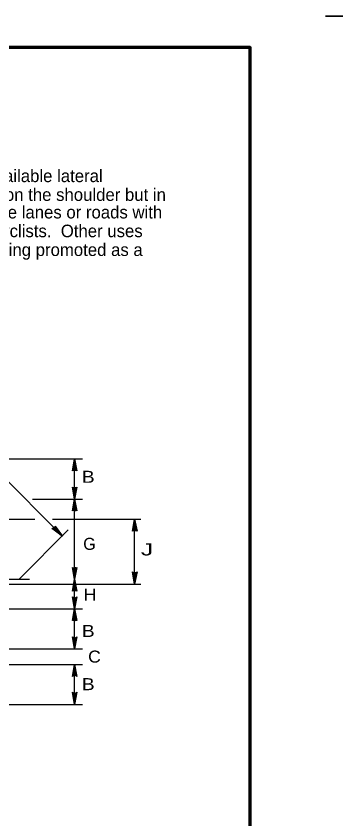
# Model space of a CAD drawing. Extents: x -0.018 to 0.195, y -0.006 to 0.263.
# Drawn here: x 0.1297 to 0.195, y 0.1026 to 0.2627 of the extents above; entities that cross this region are included whole.
import ezdxf
from ezdxf.enums import TextEntityAlignment as Align

# ---------------------------------------------------------------- set-up
doc = ezdxf.new("R2010")
doc.units = 0
doc.header["$LTSCALE"] = 0.00096
doc.linetypes.add('DOT_DASHED', pattern=[7.7, 5, -1.2, 0.3, -1.2])
doc.layers.add('1', color=7, linetype='Continuous', lineweight=25)
doc.layers.add('3', color=7, linetype='Continuous', lineweight=35)

msp = doc.modelspace()

# ---------------------------------------------------------------- linework, layer by layer
at = {"layer": '1', "lineweight": 35}
msp.add_line((0.195, 0.26275), (0.1915, 0.26275), dxfattribs=at)
at = {"layer": '1'}
for p, q in [((0.119, 0.179), (0.139, 0.159)), ((0.12525, 0.17438), (0.143, 0.17438)), ((0.14138, 0.16637), (0.14138, 0.17438)), ((0.133, 0.16637), (0.143, 0.16637)), ((0.14138, 0.15038), (0.14138, 0.16637)), ((0.1135, 0.16237), (0.1335, 0.16237)), ((0.137, 0.16237), (0.15463, 0.16237)), ((0.15338, 0.14938), (0.15338, 0.16237)), ((0.13037, 0.15038), (0.14012, 0.16025)), ((0.11213, 0.14938), (0.15463, 0.14938)), ((0.14138, 0.1445), (0.14138, 0.15038)), ((0.09788, 0.1445), (0.143, 0.1445)), ((0.14138, 0.1365), (0.14138, 0.1445)), ((0.09788, 0.1365), (0.143, 0.1365)), ((0.10138, 0.13337), (0.143, 0.13337)), ((0.14138, 0.12537), (0.14138, 0.13337)), ((0.10138, 0.12537), (0.143, 0.12537))]:
    msp.add_line(p, q, dxfattribs=at)
at = {"layer": '1', "linetype": 'DOT_DASHED'}
msp.add_line((0.03238, 0.15038), (0.14313, 0.15038), dxfattribs=at)
at = {"layer": '1', "lineweight": 70}
msp.add_lwpolyline([(0, 0), (0.1765, 0), (0.1765, 0.2565), (0, 0.2565)], close=True, dxfattribs=at)
at = {"layer": '1'}
for points in [[(0.14125, 0.17213), (0.14138, 0.17213), (0.14138, 0.17438), (0.14125, 0.17213), (0.141, 0.172), (0.14138, 0.17438), (0.1415, 0.17213), (0.14163, 0.17213), (0.14138, 0.17438), (0.14188, 0.172), (0.14163, 0.17213)], [(0.14163, 0.16862), (0.1415, 0.16862), (0.14138, 0.16637), (0.14163, 0.16862), (0.14188, 0.16875), (0.14138, 0.16637), (0.14138, 0.16862), (0.14125, 0.16862), (0.14138, 0.16637), (0.141, 0.16875), (0.14125, 0.16862)], [(0.14125, 0.16412), (0.14138, 0.16412), (0.14138, 0.16637), (0.14125, 0.16412), (0.141, 0.164), (0.14138, 0.16637), (0.1415, 0.16412), (0.14163, 0.16412), (0.14138, 0.16637), (0.14188, 0.164), (0.14163, 0.16412)], [(0.15325, 0.16012), (0.15338, 0.16012), (0.15338, 0.16237), (0.15325, 0.16012), (0.153, 0.16), (0.15338, 0.16237), (0.1535, 0.16012), (0.15363, 0.16012), (0.15338, 0.16237), (0.15388, 0.16), (0.15363, 0.16012)], [(0.1375, 0.16075), (0.1375, 0.16062), (0.139, 0.159), (0.1375, 0.16075), (0.1375, 0.161), (0.139, 0.159), (0.13725, 0.1605), (0.137, 0.1605), (0.139, 0.159), (0.13687, 0.1605), (0.137, 0.1605)], [(0.14163, 0.15263), (0.1415, 0.15263), (0.14138, 0.15038), (0.14163, 0.15263), (0.14188, 0.15275), (0.14138, 0.15038), (0.14138, 0.15263), (0.14125, 0.15263), (0.14138, 0.15038), (0.141, 0.15275), (0.14125, 0.15263)], [(0.15363, 0.15163), (0.1535, 0.15163), (0.15338, 0.14938), (0.15363, 0.15163), (0.15388, 0.15188), (0.15338, 0.14938), (0.15338, 0.15163), (0.15325, 0.15163), (0.15338, 0.14938), (0.153, 0.15188), (0.15325, 0.15163)], [(0.14125, 0.14813), (0.14138, 0.14813), (0.14138, 0.15038), (0.14125, 0.14813), (0.141, 0.148), (0.14138, 0.15038), (0.1415, 0.14813), (0.14163, 0.14813), (0.14138, 0.15038), (0.14188, 0.148), (0.14163, 0.14813)], [(0.14163, 0.14675), (0.1415, 0.1465), (0.14138, 0.1445), (0.14163, 0.14675), (0.14188, 0.14688), (0.14138, 0.1445), (0.14138, 0.1465), (0.14125, 0.14675), (0.14138, 0.1445), (0.141, 0.14688), (0.14125, 0.14675)], [(0.14125, 0.14213), (0.14138, 0.14225), (0.14138, 0.1445), (0.14125, 0.14213), (0.141, 0.14213), (0.14138, 0.1445), (0.1415, 0.14225), (0.14163, 0.14213), (0.14138, 0.1445), (0.14188, 0.14213), (0.14163, 0.14213)], [(0.14163, 0.13875), (0.1415, 0.1385), (0.14138, 0.1365), (0.14163, 0.13875), (0.14188, 0.13887), (0.14138, 0.1365), (0.14138, 0.1385), (0.14125, 0.13875), (0.14138, 0.1365), (0.141, 0.13887), (0.14125, 0.13875)], [(0.14125, 0.13125), (0.14138, 0.13125), (0.14138, 0.13337), (0.14125, 0.13125), (0.141, 0.131), (0.14138, 0.13337), (0.1415, 0.13125), (0.14163, 0.13125), (0.14138, 0.13337), (0.14188, 0.131), (0.14163, 0.13125)], [(0.14163, 0.12762), (0.1415, 0.12762), (0.14138, 0.12537), (0.14163, 0.12762), (0.14188, 0.12787), (0.14138, 0.12537), (0.14138, 0.12762), (0.14125, 0.12762), (0.14138, 0.12537), (0.141, 0.12787), (0.14125, 0.12762)]]:
    msp.add_lwpolyline(points, dxfattribs=at)

# ---------------------------------------------------------------- texts
for s, width, p in [('B', 1.2, (0.14413, 0.16962)), ('J', 1.55, (0.15588, 0.15513)), ('H', 1.1, (0.1445, 0.14613)), ('B', 1.2, (0.14413, 0.13887)), ('C', 1.1, (0.14538, 0.13375)), ('B', 1.2, (0.14413, 0.12825))]:
    msp.add_text(s, height=0.0024, dxfattribs=dict(at, width=width)).set_placement(p, align=Align.CENTER)
msp.add_text('G', height=0.0024, dxfattribs=at).set_placement((0.14438, 0.15625), align=Align.CENTER)
at = {"layer": '3'}
for s, p in [('     The Share the Road Sign (W15-3) may be used on highways where available lateral', (0.01787, 0.22962)), ('clearances make it likely that bicyclists will either travel on the roadway or on the shoulder but in', (0.01787, 0.22587)), ('close proximity to the roadway.  It may also be used in conjunction with bike lanes or roads with', (0.01787, 0.22237)), ('wide paved shoulders if the intent is to alert motorists to the presence of cyclists.  Other uses', (0.01787, 0.21863)), ('may include roads with a documented car-bike crash history and a road being promoted as a', (0.01787, 0.21488))]:
    msp.add_text(s, height=0.0025, dxfattribs=at).set_placement(p)

doc.saveas('drawing.dxf')
